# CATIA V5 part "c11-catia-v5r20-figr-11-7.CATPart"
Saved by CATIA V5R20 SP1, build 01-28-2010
Part number: Part1
Bounding box of the stored display mesh (mm): x -50 to 50, y -39.834 to 41.856, z -25 to 25
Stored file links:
  D:\v5_r20\psrt_files_downloaded\c11\c11-catia-v5r20-figr-11-7.CATPart
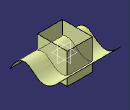
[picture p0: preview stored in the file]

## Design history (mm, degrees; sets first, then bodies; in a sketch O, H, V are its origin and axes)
Set1
  Sketch1 on yz-plane, origin (0, 0, 0), H (0, 1, 0), V (0, 0, 1)
    spline S1 through (-39.8338, -18.0686) (-4.7892, 0) (1.9431, -5.3632) (41.8556, 3.6938)
    point P1 (-4.7892, 0)
    coincidence: P1 H
  Extrude1: Element1 Sketch1, Lim1 50, Lim2 50, Direction yz-plane
  Sketch2 on xy-plane, origin (0, 0, 0), H (1, 0, 0), V (0, 1, 0)
    line L1 (-20.1634, 25.5896) -> (20.7534, 25.5896)
    line L2 (20.7534, 25.5896) -> (20.7534, -23.3463)
    line L3 (20.7534, -23.3463) -> (-20.1634, -23.3463)
    line L4 (-20.1634, -23.3463) -> (-20.1634, 25.5896)
    horizontal: L1 H, L3 H
    vertical: L2 V, L4 V
  Extrude2: Element1 Sketch2, Lim1 25, Lim2 25, Direction xy-plane
  Intersect1: ToIntersect1 Extrude1, ToIntersect2 Extrude2
Body1 (main body)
